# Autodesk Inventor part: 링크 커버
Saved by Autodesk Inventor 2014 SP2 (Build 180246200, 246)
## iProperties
Created: 2025-07
Part Number: 링크 커버
Material: Generic
Document SubType Name: Modeling
Designer: Administrator
Density: 1 g/cm^3
Appearance: Default
Author: Administrator
Author: jhkim
Creation Date: 2025-06-11
Sending System: Autodesk Inventor 2026
Preprocessor: ST-DEVELOPER v20.1
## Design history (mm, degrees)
node "링크 커버1"
node "솔리드1"
node "기준1"
